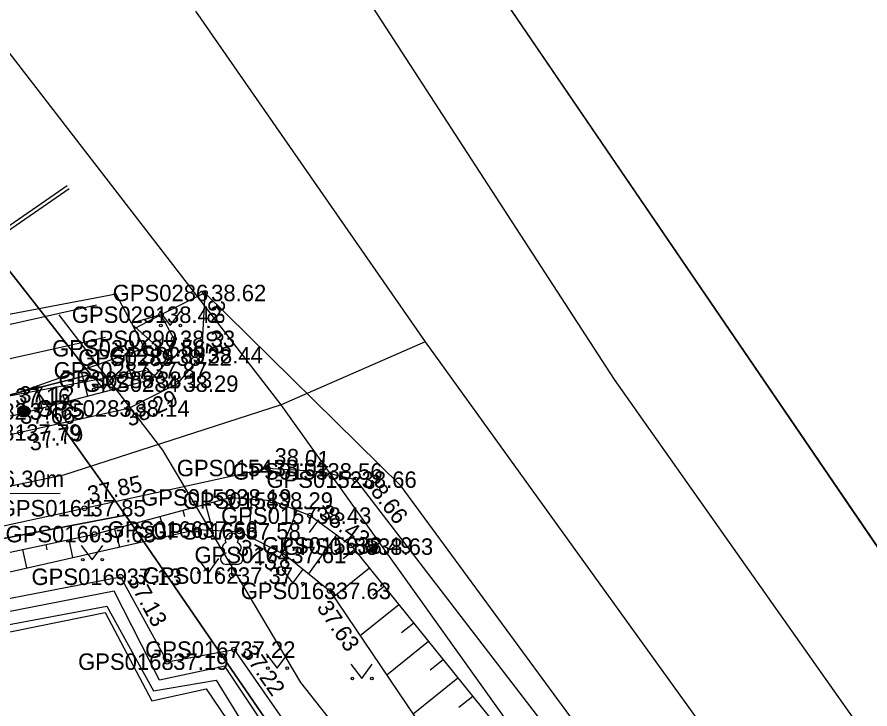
# Model space of a CAD drawing. Extents: x 626224 to 628280, y 6467750 to 6471135.
# Drawn here: x 627683.58 to 627719.8, y 6468618.54 to 6468647.94 of the extents above; entities that cross this region are included whole.
import ezdxf

# ---------------------------------------------------------------- set-up
doc = ezdxf.new("R2010")
doc.units = 0
for name, color, linetype in [('HALJASTUS', 7, 'Continuous'), ('KORGUS-EH2000', 7, 'Continuous'), ('KPKAABEL', 7, 'Continuous'), ('MOOTKORG-EH2000', 7, 'Continuous'), ('MOOTMPUNKT', 7, 'Continuous'), ('MOOTNR', 7, 'Continuous'), ('MOOTPIIR', 7, 'Continuous'), ('MPKAABEL', 7, 'Continuous'), ('PIIR', 7, 'Continuous'), ('POST', 7, 'Continuous'), ('PUU', 7, 'Continuous'), ('RAJATIS', 7, 'Continuous'), ('RELJEEF', 7, 'Continuous'), ('SITRASS', 7, 'Continuous'), ('TEE', 7, 'Continuous'), ('Tee Liiklusala', 7, 'Continuous'), ('Tee Muu tee Püsikate', 7, 'Continuous'), ('Tee Põhimaantee Püsikate', 7, 'Continuous')]:
    doc.layers.add(name, color=color, linetype=linetype)

msp = doc.modelspace()

# ---------------------------------------------------------------- linework, layer by layer
at = {"layer": 'HALJASTUS'}
for p, q in [((627689.619, 6468635.444), (627690.082, 6468634.837)), ((627690.082, 6468634.837), (627690.528, 6468635.444)), ((627686.777, 6468632.723), (627687.24, 6468632.116)), ((627687.24, 6468632.116), (627687.686, 6468632.723)), ((627686.303, 6468625.491), (627686.767, 6468624.885)), ((627686.767, 6468624.885), (627687.212, 6468625.491)), ((627691.237, 6468624.939), (627691.701, 6468624.332)), ((627691.701, 6468624.332), (627692.146, 6468624.939)), ((627694.818, 6468624.487), (627695.282, 6468623.88)), ((627695.282, 6468623.88), (627695.727, 6468624.487)), ((627694.16, 6468620.882), (627694.624, 6468620.275)), ((627694.624, 6468620.275), (627695.069, 6468620.882)), ((627697.754, 6468620.44), (627698.217, 6468619.833)), ((627698.217, 6468619.833), (627698.663, 6468620.44))]:
    msp.add_line(p, q, dxfattribs=at)
for points in [[(627664.314, 6468627.994), (627663.863, 6468630.771), (627664.725, 6468631.383), (627673.353, 6468632.664), (627686.946, 6468635.712)], [(627664.47, 6468629.471), (627674.392, 6468631.453), (627687.331, 6468634.332)], [(627689.052, 6468632.927), (627683.236, 6468631.825), (627675.654, 6468629.762), (627664.314, 6468627.994)], [(627673.61, 6468619.969), (627672.976, 6468621.286), (627679.187, 6468622.456), (627687.969, 6468624.157), (627689.948, 6468620.551), (627692.796, 6468621.064), (627698.292, 6468613.159), (627705.989, 6468601.538), (627717.166, 6468585.678)], [(627716.572, 6468584.873), (627705.028, 6468601.396), (627692.406, 6468620.356), (627689.621, 6468619.759), (627687.703, 6468623.543), (627673.321, 6468620.739)], [(627673.61, 6468619.969), (627679.701, 6468621.092), (627687.315, 6468622.642), (627689.297, 6468618.889), (627691.61, 6468619.392), (627696.609, 6468612.017), (627704.309, 6468600.39), (627715.503, 6468584.506)]]:
    msp.add_lwpolyline(points, dxfattribs=at)
for centre in [(627689.681, 6468634.837), (627690.51, 6468634.837), (627686.839, 6468632.116), (627687.668, 6468632.116), (627686.366, 6468624.885), (627687.195, 6468624.885), (627691.3, 6468624.332), (627692.129, 6468624.332), (627694.881, 6468623.88), (627695.709, 6468623.88), (627694.223, 6468620.275), (627695.052, 6468620.275), (627697.816, 6468619.833), (627698.645, 6468619.833)]:
    msp.add_circle(centre, 0.055, dxfattribs=at)
at = {"layer": 'KORGUS-EH2000'}
for centre in [(627691.556, 6468636.216), (627690.377, 6468632.362), (627683.705, 6468630.285), (627694.212, 6468628.779), (627697.947, 6468628.287), (627686.437, 6468627.071), (627696.02, 6468626.757), (627693.024, 6468626.089), (627687.969, 6468624.157), (627696.853, 6468623.559), (627692.796, 6468621.064)]:
    msp.add_circle(centre, 0.1, dxfattribs=at)
at = {"layer": 'KPKAABEL'}
msp.add_lwpolyline([(627685.782, 6468640.643), (627682.599, 6468638.441), (627678.043, 6468635.809), (627672.046, 6468634.344), (627660.214, 6468631.662), (627657.997, 6468630.954), (627658.117, 6468626.708), (627657.689, 6468626.13), (627652.495, 6468625.008), (627640.455, 6468623.259), (627628.481, 6468622.246), (627623.048, 6468622.007), (627612.632, 6468622.516), (627609.034, 6468622.858), (627605.474, 6468623.034), (627601.854, 6468622.409), (627599.956, 6468622.4), (627599.775, 6468623.347)], dxfattribs=at)
at = {"layer": 'MOOTMPUNKT'}
for centre in [(627691.556, 6468636.216), (627689.682, 6468635.294), (627690.235, 6468634.267), (627688.985, 6468633.865), (627690.092, 6468633.472), (627691.411, 6468633.572), (627689.052, 6468632.927), (627689.259, 6468632.526), (627690.377, 6468632.362), (627688.302, 6468631.311), (627683.853, 6468631.183), (627683.705, 6468630.285), (627694.212, 6468628.779), (627696.498, 6468628.635), (627697.947, 6468628.287), (627692.626, 6468627.53), (627694.391, 6468627.395), (627686.437, 6468627.071), (627696.02, 6468626.757), (627686.866, 6468625.972), (627691.199, 6468626.166), (627693.024, 6468626.089), (627697.766, 6468625.488), (627698.644, 6468625.44), (627694.96, 6468625.086), (627687.969, 6468624.157), (627692.693, 6468624.21), (627696.853, 6468623.559), (627692.796, 6468621.064), (627689.948, 6468620.551)]:
    msp.add_circle(centre, 0.1, dxfattribs=at)
at = {"layer": 'MOOTPIIR'}
for points in [[(627725.17, 6468593.561), (627699.891, 6468628.007), (627691.556, 6468636.216), (627689.682, 6468635.294), (627688.429, 6468634.933), (627687.779, 6468636.161), (627663.981, 6468631.653), (627656.533, 6468628.521), (627633.238, 6468625.152)], [(627644.92, 6468614.927), (627687.389, 6468622.904), (627689.377, 6468619.311), (627692.038, 6468619.76), (627702.956, 6468602.021), (627695.606, 6468595.477), (627701.992, 6468581.333), (627711.232, 6468581.738), (627717.166, 6468585.678), (627720.646, 6468589.364)]]:
    msp.add_lwpolyline(points, dxfattribs=at)
at = {"layer": 'MPKAABEL'}
for points in [[(627685.699, 6468640.768), (627682.519, 6468638.568), (627677.987, 6468635.95), (627672.012, 6468634.49), (627660.175, 6468631.807), (627657.844, 6468631.063), (627657.966, 6468626.756), (627657.602, 6468626.265), (627652.468, 6468625.156), (627640.438, 6468623.408), (627628.471, 6468622.396), (627623.048, 6468622.157), (627612.643, 6468622.666), (627609.045, 6468623.008), (627605.465, 6468623.185), (627601.841, 6468622.559), (627601.344, 6468627.176), (627599.992, 6468627.142), (627599.551, 6468626.364)], [(627685.401, 6468627.702), (627679.495, 6468627.683), (627676.897, 6468626.445)]]:
    msp.add_lwpolyline(points, dxfattribs=at)
at = {"layer": 'PIIR'}
for points in [[(627433.19, 6469529.94), (627459.99, 6469400.72), (627467.62, 6469361.51), (627515.86, 6469120.25), (627514.14, 6469119.89), (627516.34, 6469107.19), (627530.89, 6469025.52), (627552.51, 6468945.46), (627573.42, 6468886.37), (627594.9, 6468837.52), (627616.28, 6468794.59), (627647.89, 6468735.54), (627664.81, 6468708.59), (627667, 6468705.1), (627666.22, 6468704.47), (627739.66, 6468596.76), (627806.32, 6468497.36)], [(627746.91, 6468541.23), (627688.18, 6468626.77), (627684.35, 6468632.16), (627686.69, 6468632.75), (627663.66, 6468662.2), (627667.34, 6468664.86), (627649.05, 6468692.73), (627646.31, 6468691.19), (627629.12, 6468721.76), (627618.92, 6468715.04), (627606.91, 6468724.16), (627579.16, 6468687.58), (627549.96, 6468707.41), (627588.77, 6468756.22), (627618.05, 6468733.86), (627619.84, 6468735.06), (627604.18, 6468764.29), (627579.83, 6468812.09), (627559.2, 6468856.67), (627547.01, 6468886.57), (627533.67, 6468925.79), (627531.86, 6468935.62), (627512.37, 6469002.4)], [(627401.5, 6468603.97), (627489.68, 6468613.41), (627577.55, 6468622.81), (627581.38, 6468622.85), (627583, 6468623.57), (627584.27, 6468624.13), (627586.23, 6468625.97), (627588.94, 6468620.18), (627605.69, 6468621.95), (627623.24, 6468621.3), (627652.69, 6468624.22), (627684.35, 6468632.16), (627688.18, 6468626.77), (627643.52, 6468618.24), (627599.49, 6468616.8), (627555.29, 6468612.05), (627411.34, 6468595.13)]]:
    msp.add_lwpolyline(points, dxfattribs=at)
for points in [[(627721.6, 6468730.39), (627736.85, 6468731.37), (627748.32, 6468730.85), (627755.06, 6468730.18), (627763.98, 6468725.35), (627769.77, 6468721.4), (627773.29, 6468719), (627779.7, 6468714.56), (627782.98, 6468713.12), (627824.63, 6468735.56), (627865.5, 6468668.3), (627739.66, 6468596.76), (627666.22, 6468704.47), (627667, 6468705.1), (627667.19, 6468705.25), (627669.44, 6468709.31), (627669.59, 6468709.46), (627678.04, 6468717.3), (627687.85, 6468721.98), (627703.09, 6468726.53)], [(627654.85, 6468663.52), (627663.66, 6468662.2), (627686.69, 6468632.75), (627684.35, 6468632.16), (627652.69, 6468624.22), (627623.24, 6468621.3), (627605.69, 6468621.95), (627588.94, 6468620.18), (627586.23, 6468625.97), (627596.31, 6468635.4), (627619.6, 6468659.76), (627624.98, 6468665.39), (627633.24, 6468674.95), (627637.73, 6468680.5), (627640.48, 6468683.65), (627644.86, 6468680.34)], [(627746.91, 6468541.23), (627666.94, 6468517.08), (627653, 6468577.43), (627643.52, 6468618.24), (627688.18, 6468626.77)]]:
    msp.add_lwpolyline(points, close=True, dxfattribs=at)
at = {"layer": 'POST'}
msp.add_line((627698.467, 6468625.263), (627698.821, 6468625.617), dxfattribs=at)
msp.add_circle((627698.644, 6468625.44), 0.25, dxfattribs=at)
for radius, start, end in [(0.225, 224.8541, 45.0356), (0.2, 224.8427, 45.047), (0.175, 224.8281, 45.0616), (0.15, 224.8087, 45.081), (0.125, 224.7814, 45.1083), (0.1, 224.7406, 45.1491), (0.075, 224.6725, 45.2172), (0.05, 224.5363, 45.3534), (0.025, 224.1278, 45.7619)]:
    msp.add_arc((627698.644, 6468625.44), radius, start, end, dxfattribs=at)
at = {"layer": 'PUU'}
for p, q in [((627692.934, 6468624.685), (627692.454, 6468624.685)), ((627692.693, 6468624.21), (627692.693, 6468624.685)), ((627693.074, 6468624.21), (627692.693, 6468624.21))]:
    msp.add_line(p, q, dxfattribs=at)
for centre, radius, start, end in [((627692.693, 6468625.73), 0.277, 332.5799, 207.4201), ((627692.523, 6468625.382), 0.233, 109.0217, 253.1415), ((627692.864, 6468625.382), 0.233, 286.8508, 70.9859), ((627692.456, 6468624.922), 0.238, 90.0016, 269.3953), ((627692.931, 6468624.922), 0.238, 270.6047, 89.9984)]:
    msp.add_arc(centre, radius, start, end, dxfattribs=at)
at = {"layer": 'RAJATIS'}
for radius in [0.25, 0.225, 0.2, 0.175, 0.15, 0.125, 0.1, 0.075, 0.05, 0.025]:
    msp.add_circle((627683.853, 6468631.183), radius, dxfattribs=at)
at = {"layer": 'RELJEEF'}
for p, q in [((627689.682, 6468635.294), (627688.556, 6468634.689)), ((627690.075, 6468633.453), (627688.458, 6468634.878)), ((627688.519, 6468632.333), (627688.192, 6468633.586)), ((627686.583, 6468631.828), (627686.299, 6468632.92)), ((627689.414, 6468632.703), (627689.095, 6468632.984)), ((627684.648, 6468631.324), (627684.405, 6468632.254)), ((627687.551, 6468632.081), (627687.459, 6468632.432)), ((627685.616, 6468631.576), (627685.537, 6468631.879)), ((627683.68, 6468631.071), (627683.614, 6468631.326)), ((627692.54, 6468627.507), (627692.655, 6468627.083)), ((627693.535, 6468627.461), (627693.415, 6468625.887)), ((627691.575, 6468627.246), (627691.875, 6468626.138)), ((627694.522, 6468627.344), (627694.324, 6468626.837)), ((627689.644, 6468626.724), (627689.876, 6468625.867)), ((627690.61, 6468626.985), (627690.683, 6468626.716)), ((627695.453, 6468626.979), (627694.753, 6468625.193)), ((627688.679, 6468626.462), (627688.745, 6468626.218)), ((627696.337, 6468626.526), (627695.986, 6468626.044)), ((627686.747, 6468625.947), (627686.795, 6468625.721)), ((627687.714, 6468626.201), (627687.924, 6468625.425)), ((627685.769, 6468625.739), (627685.931, 6468624.974)), ((627697.146, 6468625.939), (627695.948, 6468624.289)), ((627683.813, 6468625.322), (627683.981, 6468624.533)), ((627684.791, 6468625.53), (627684.84, 6468625.297)), ((627697.912, 6468625.306), (627697.428, 6468624.916)), ((627698.539, 6468624.527), (627697.024, 6468623.307)), ((627699.166, 6468623.748), (627698.692, 6468623.367)), ((627699.794, 6468622.969), (627698.149, 6468621.645)), ((627700.421, 6468622.19), (627699.908, 6468621.778)), ((627701.048, 6468621.412), (627699.274, 6468619.984)), ((627701.675, 6468620.633), (627701.123, 6468620.189)), ((627702.302, 6468619.854), (627700.399, 6468618.322)), ((627702.929, 6468619.075), (627702.339, 6468618.6))]:
    msp.add_line(p, q, dxfattribs=at)
for points in [[(627689.682, 6468635.294), (627690.235, 6468634.267), (627690.092, 6468633.472), (627689.259, 6468632.526), (627683.446, 6468631.01), (627675.445, 6468629.871)], [(627688.429, 6468634.933), (627688.985, 6468633.865), (627683.41, 6468631.904), (627675.465, 6468630.016)], [(627664.293, 6468620.969), (627678.559, 6468624.205), (627686.866, 6468625.972), (627692.626, 6468627.53), (627694.391, 6468627.395), (627696.02, 6468626.757), (627697.766, 6468625.488), (627704.517, 6468617.101), (627712.652, 6468604.661), (627723.007, 6468591.238)], [(627664.284, 6468620.85), (627678.877, 6468623.378), (627691.199, 6468626.166), (627693.024, 6468626.089), (627694.96, 6468625.086), (627696.853, 6468623.559), (627702.288, 6468615.532), (627710.843, 6468603.567), (627720.646, 6468589.364)]]:
    msp.add_lwpolyline(points, dxfattribs=at)
at = {"layer": 'SITRASS'}
msp.add_lwpolyline([(627718.499, 6468587.089), (627713.907, 6468593.848), (627710.374, 6468599.048), (627699.564, 6468614.681), (627695.628, 6468619.665), (627689.767, 6468629.543), (627685.369, 6468635.281)], dxfattribs=at)
at = {"layer": 'TEE'}
msp.add_lwpolyline([(627691.556, 6468636.216), (627691.411, 6468633.572), (627690.377, 6468632.362), (627688.302, 6468631.311), (627683.705, 6468630.285), (627675.534, 6468628.326), (627664.963, 6468626.349), (627655.323, 6468624.553), (627656.855, 6468621.064), (627660.849, 6468621.603), (627663.795, 6468622.181), (627671.677, 6468623.939), (627678.512, 6468625.342), (627686.437, 6468627.071), (627694.212, 6468628.779), (627696.498, 6468628.635), (627697.947, 6468628.287), (627705.762, 6468618.126), (627714.785, 6468606.184), (627724.497, 6468592.392)], dxfattribs=at)
at = {"layer": 'Tee Liiklusala'}
for points in [[(627542.306, 6468967.371), (627548.71, 6468942.84), (627554.3, 6468925.9), (627578.18, 6468861.63), (627588.31, 6468840.05), (627629.52, 6468759.1), (627656.29, 6468714.41), (627663.537, 6468702.423), (627687.78, 6468662.54), (627695.93, 6468652.611), (627708.93, 6468632.54), (627721.86, 6468614.22), (627748.47, 6468578.42), (627760.92, 6468560.36), (627780.56, 6468531.91)], [(627770.48, 6468525.39), (627740.557, 6468568.764), (627738.71, 6468571.44), (627735.13, 6468576.26), (627712.14, 6468607.18), (627694.794, 6468631.457), (627678.044, 6468653.167), (627666.826, 6468668.407), (627651.484, 6468693.118), (627649.736, 6468695.878), (627641.743, 6468708.498), (627640.999, 6468709.875), (627623.478, 6468742.312), (627616.983, 6468754.336), (627595.384, 6468797.487), (627592.828, 6468802.833), (627577.59, 6468834.7), (627567.06, 6468857.03), (627562.51, 6468869.71), (627561.06, 6468873.68), (627543.04, 6468921.76), (627539.249, 6468933.164), (627537.18, 6468939.44), (627530.65, 6468964.53)]]:
    msp.add_lwpolyline(points, dxfattribs=at)
at = {"layer": 'Tee Muu tee Püsikate'}
msp.add_lwpolyline([(627700.902, 6468634.138), (627694.794, 6468631.457), (627685.552, 6468628.47), (627661.394, 6468623.428), (627655.281, 6468622.513)], dxfattribs=at)
at = {"layer": 'Tee Põhimaantee Püsikate'}
for points in [[(627691.161, 6468648.196), (627700.902, 6468634.138)], [(627700.902, 6468634.138), (627743.449, 6468575.098), (627775.098, 6468528.301), (627799.448, 6468490.206), (627812.119, 6468468.847)]]:
    msp.add_lwpolyline(points, dxfattribs=at)

# ---------------------------------------------------------------- texts
at = {"layer": 'KORGUS-EH2000'}
for s, rotation, p in [(' 38.62', 266.8739, (627691.731, 6468636.207)), (' 38.29', 25.0089, (627688.122, 6468630.401)), (' 37.79', 12.0283, (627683.9, 6468629.432)), (' 38.01', 356.4046, (627694.223, 6468628.954)), (' 38.66', 307.5601, (627698.086, 6468628.394)), (' 37.85', 12.3897, (627686.4, 6468627.242)), (' 38.43', 324.0089, (627696.122, 6468626.898)), (' 37.58', 332.6161, (627692.621, 6468625.312)), (' 37.13', 298.7496, (627688.123, 6468624.242)), (' 37.63', 304.1035, (627696.129, 6468623.068)), (' 37.22', 304.8123, (627692.94, 6468621.163))]:
    msp.add_text(s, height=0.7, rotation=rotation, dxfattribs=at).set_placement(p)
at = {"layer": 'MOOTKORG-EH2000'}
for s, p in [(' 38.62', (627691.556, 6468635.866)), (' 38.42', (627689.682, 6468634.944)), (' 38.33', (627690.235, 6468633.917)), (' 37.56', (627688.985, 6468633.515)), (' 38.44', (627691.411, 6468633.222)), (' 38.22', (627690.092, 6468633.122)), (' 37.87', (627689.052, 6468632.577)), (' 38.13', (627689.259, 6468632.176)), (' 38.29', (627690.377, 6468632.012)), (' 37.16', (627683.236, 6468631.475)), (' 37.12', (627683.41, 6468631.554)), (' 37.65', (627683.853, 6468630.833)), (' 38.14', (627688.302, 6468630.961)), (' 37.66', (627683.446, 6468630.66)), (' 37.79', (627683.705, 6468629.935)), (' 38.01', (627694.212, 6468628.429)), (' 38.56', (627696.498, 6468628.285)), (' 38.66', (627697.947, 6468627.937)), (' 38.19', (627692.626, 6468627.18)), (' 38.29', (627694.391, 6468627.046)), (' 37.85', (627686.437, 6468626.721)), (' 38.43', (627696.02, 6468626.406)), (' 37.68', (627686.866, 6468625.622)), (' 37.66', (627691.199, 6468625.816)), (' 37.58', (627693.024, 6468625.739)), (' 38.49', (627697.766, 6468625.138)), (' 38.63', (627698.644, 6468625.09)), (' 37.61', (627694.96, 6468624.736)), (' 37.13', (627687.969, 6468623.808)), (' 37.37', (627692.693, 6468623.86)), (' 37.63', (627696.853, 6468623.209)), (' 37.22', (627692.796, 6468620.714)), (' 37.19', (627689.948, 6468620.201))]:
    msp.add_text(s, height=0.7, dxfattribs=at).set_placement(p)
at = {"layer": 'MOOTNR'}
for s, p in [('GPS0286 ', (627687.636, 6468635.866)), ('GPS0291 ', (627685.902, 6468634.944)), ('GPS0290 ', (627686.315, 6468633.917)), ('GPS0292 ', (627685.065, 6468633.515)), ('GPS0285 ', (627687.492, 6468633.222)), ('GPS0289 ', (627686.173, 6468633.122)), ('GPS0287 ', (627685.132, 6468632.577)), ('GPS0288 ', (627685.339, 6468632.176)), ('GPS0284 ', (627686.387, 6468632.012)), ('GPS0282 ', (627679.933, 6468630.833)), ('GPS0283 ', (627684.382, 6468630.961)), ('GPS0281 ', (627679.925, 6468629.935)), ('GPS0154 ', (627690.362, 6468628.429)), ('GPS0153 ', (627692.718, 6468628.285)), ('GPS0152 ', (627694.168, 6468627.937)), ('GPS0159 ', (627688.846, 6468627.18)), ('GPS0158 ', (627690.611, 6468627.046)), ('GPS0161 ', (627682.797, 6468626.721)), ('GPS0157 ', (627692.24, 6468626.406)), ('GPS0160 ', (627683.087, 6468625.622)), ('GPS0166 ', (627687.419, 6468625.816)), ('GPS0165 ', (627689.244, 6468625.739)), ('GPS0156 ', (627693.986, 6468625.138)), ('GPS0155 ', (627694.864, 6468625.09)), ('GPS0164 ', (627691.111, 6468624.736)), ('GPS0169 ', (627684.189, 6468623.808)), ('GPS0162 ', (627688.914, 6468623.86)), ('GPS0163 ', (627693.074, 6468623.209)), ('GPS0167 ', (627689.016, 6468620.714)), ('GPS0168 ', (627686.168, 6468620.201))]:
    msp.add_text(s, height=0.7, dxfattribs=at).set_placement(p)
at = {"layer": 'MPKAABEL'}
msp.add_text('õhuliin +6.30m', height=0.7, dxfattribs=at).set_placement((627679.457, 6468627.969))

doc.saveas('drawing.dxf')
